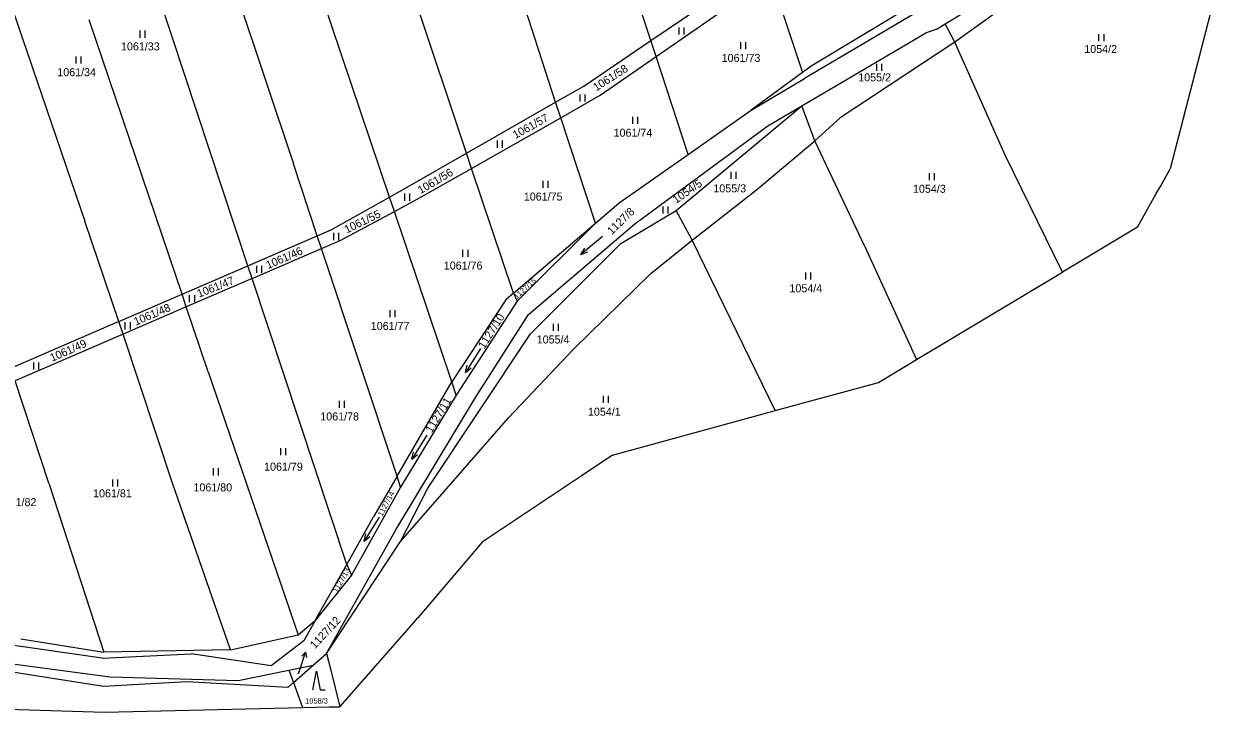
# Model space of a CAD drawing. Extents: x -794142 to -791199, y -1109267 to -1105626.
# Drawn here: x -791483.8 to -791231.1, y -1109118.2 to -1108972 of the extents above; entities that cross this region are included whole.
import ezdxf

# ---------------------------------------------------------------- set-up
doc = ezdxf.new("R2010")
doc.units = 0
for name, color, linetype in [('Komunikace', 7, 'Continuous'), ('Vrstva 1', 7, 'Continuous'), ('Vrstva 14', 7, 'Continuous'), ('Vrstva 16', 7, 'Continuous'), ('Vrstva 23', 7, 'Continuous'), ('Vrstva 4', 7, 'Continuous')]:
    doc.layers.add(name, color=color, linetype=linetype)

msp = doc.modelspace()

# ---------------------------------------------------------------- linework, layer by layer
at = {"layer": 'Komunikace'}
msp.add_line((-791425.42, -1109109.98), (-791424.87, -1109108.32), dxfattribs=at)
at = {"layer": 'Vrstva 1'}
for p, q in [((-791406.1, -1109008.8), (-791438.95, -1108911.62)), ((-791454.92, -1108916.61), (-791426.53, -1109001.71)), ((-791436.19, -1109023.39), (-791469.39, -1108923.1)), ((-791497.78, -1108934.85), (-791470.8, -1109013.94)), ((-791350.58, -1108975.51), (-791363.36, -1108936.25)), ((-791370.82, -1108988.65), (-791384.24, -1108946.84)), ((-791258.33, -1108956.04), (-791286.05, -1108975.86)), ((-791350.58, -1108975.51), (-791326.18, -1108958.88)), ((-791349.46, -1108978.94), (-791325.12, -1108962.07)), ((-791325.12, -1108962.07), (-791318.37, -1108982.33)), ((-791280, -1108961.18), (-791317.94, -1108983.62)), ((-791389.76, -1108999.49), (-791401.54, -1108964.23)), ((-791288.06, -1108972.01), (-791274.69, -1108963.9)), ((-791294.17, -1108967.57), (-791316.56, -1108981)), ((-791450.19, -1109029.44), (-791469.89, -1108971.15)), ((-791292.04, -1108973.81), (-791289.78, -1108973.05)), ((-791289.78, -1108973.05), (-791288.06, -1108972.01)), ((-791286.05, -1108975.86), (-791288.06, -1108972.01)), ((-791364.83, -1108985.22), (-791350.58, -1108975.51)), ((-791349.46, -1108978.94), (-791350.58, -1108975.51)), ((-791318.51, -1108989.39), (-791292.04, -1108973.81)), ((-791286.05, -1108975.86), (-791310.37, -1108991.93)), ((-791275.33, -1108999.92), (-791286.05, -1108975.86)), ((-791361.33, -1108987.16), (-791349.46, -1108978.94)), ((-791342.69, -1108999.76), (-791349.46, -1108978.94)), ((-791316.56, -1108981), (-791318.37, -1108982.33)), ((-791318.37, -1108982.33), (-791329.3, -1108990.34)), ((-791329.3, -1108990.34), (-791317.94, -1108983.62)), ((-791370.82, -1108988.65), (-791364.83, -1108985.22)), ((-791389.76, -1108999.49), (-791370.82, -1108988.65)), ((-791369.74, -1108991.94), (-791370.82, -1108988.65)), ((-791369.74, -1108991.94), (-791361.33, -1108987.16)), ((-791345.22, -1109011.67), (-791318.51, -1108989.39)), ((-791342.69, -1108999.76), (-791329.3, -1108990.34)), ((-791325.74, -1108993.65), (-791318.51, -1108989.39)), ((-791315.73, -1108996.82), (-791318.51, -1108989.39)), ((-791388.68, -1109002.7), (-791369.74, -1108991.94)), ((-791362.36, -1109014.36), (-791369.74, -1108991.94)), ((-791354, -1109014.49), (-791325.74, -1108993.65)), ((-791315.73, -1108996.82), (-791310.37, -1108991.93)), ((-791328.13, -1109007.25), (-791315.73, -1108996.82)), ((-791305.11, -1109019.28), (-791315.73, -1108996.82)), ((-791401.89, -1109006.43), (-791389.76, -1108999.49)), ((-791388.68, -1109002.7), (-791389.76, -1108999.49)), ((-791357.29, -1109010.04), (-791342.69, -1108999.76)), ((-791263.18, -1109024.75), (-791275.33, -1108999.92)), ((-791421.45, -1109017.02), (-791426.53, -1109001.71)), ((-791400.23, -1109009.27), (-791388.68, -1109002.7)), ((-791379.75, -1109029.18), (-791388.68, -1109002.7)), ((-791406.1, -1109008.8), (-791401.89, -1109006.43)), ((-791418.48, -1109015.74), (-791406.1, -1109008.8)), ((-791405.07, -1109011.85), (-791406.1, -1109008.8)), ((-791341.84, -1109017.96), (-791328.13, -1109007.25)), ((-791405.07, -1109011.85), (-791400.23, -1109009.27)), ((-791362.36, -1109014.36), (-791357.29, -1109010.04)), ((-791463.58, -1109035.23), (-791470.8, -1109013.94)), ((-791416.6, -1109018), (-791405.07, -1109011.85)), ((-791392.84, -1109048.04), (-791405.07, -1109011.85)), ((-791356.97, -1109018.62), (-791345.22, -1109011.67)), ((-791341.84, -1109017.96), (-791345.22, -1109011.67)), ((-791421.45, -1109017.02), (-791418.48, -1109015.74)), ((-791379.75, -1109029.18), (-791362.36, -1109014.36)), ((-791379, -1109030.9), (-791362.36, -1109014.36)), ((-791376.55, -1109033.76), (-791354, -1109014.49)), ((-791436.19, -1109023.39), (-791421.45, -1109017.02)), ((-791420.56, -1109019.71), (-791421.45, -1109017.02)), ((-791420.56, -1109019.71), (-791416.6, -1109018)), ((-791376.13, -1109037.8), (-791356.97, -1109018.62)), ((-791350.58, -1109025.02), (-791341.84, -1109017.96)), ((-791324.17, -1109054.09), (-791341.84, -1109017.96)), ((-791435.3, -1109026.08), (-791420.56, -1109019.71)), ((-791404.5, -1109068.08), (-791420.56, -1109019.71)), ((-791305.11, -1109019.28), (-791294.15, -1109043.3)), ((-791450.19, -1109029.44), (-791436.19, -1109023.39)), ((-791435.3, -1109026.08), (-791436.19, -1109023.39)), ((-791435.3, -1109026.08), (-791449.28, -1109032.12)), ((-791415.2, -1109086.82), (-791435.3, -1109026.08)), ((-791350.58, -1109025.02), (-791366.92, -1109040.99)), ((-791379.75, -1109029.18), (-791381.4, -1109030.59)), ((-791379.75, -1109029.18), (-791379, -1109030.9)), ((-791463.58, -1109035.23), (-791450.19, -1109029.44)), ((-791449.28, -1109032.12), (-791450.19, -1109029.44)), ((-791381.4, -1109030.59), (-791392.84, -1109048.04)), ((-791379, -1109030.9), (-791391.95, -1109050.83)), ((-791449.28, -1109032.12), (-791462.67, -1109037.91)), ((-791444.61, -1109045.94), (-791449.28, -1109032.12)), ((-791387.82, -1109051.33), (-791376.55, -1109033.76)), ((-791463.58, -1109035.23), (-791486.5, -1109045.13)), ((-791462.67, -1109037.91), (-791463.58, -1109035.23)), ((-791462.67, -1109037.91), (-791485.62, -1109047.82)), ((-791452.23, -1109069.55), (-791462.67, -1109037.91)), ((-791397.97, -1109070.59), (-791376.13, -1109037.8)), ((-791366.92, -1109040.99), (-791380.83, -1109055.65)), ((-791444.61, -1109045.94), (-791425.48, -1109101.75)), ((-791478.5, -1109069.56), (-791485.62, -1109047.82)), ((-791404.5, -1109068.08), (-791392.84, -1109048.04)), ((-791391.95, -1109050.83), (-791392.84, -1109048.04)), ((-791404.74, -1109079.43), (-791387.82, -1109051.33)), ((-791391.95, -1109050.83), (-791403.74, -1109070.4)), ((-791403.79, -1109081.97), (-791380.83, -1109055.65)), ((-791478.5, -1109069.56), (-791466.81, -1109105.45)), ((-791439.91, -1109104.97), (-791452.23, -1109069.55)), ((-791404.5, -1109068.08), (-791409.5, -1109076.67)), ((-791403.74, -1109070.4), (-791404.5, -1109068.08)), ((-791403.74, -1109070.4), (-791414.21, -1109089.1)), ((-791403.79, -1109081.97), (-791397.97, -1109070.59)), ((-791415.2, -1109086.82), (-791409.5, -1109076.67)), ((-791419.48, -1109105.71), (-791404.74, -1109079.43)), ((-791419.48, -1109105.71), (-791403.79, -1109081.97)), ((-791421.88, -1109098.73), (-791415.2, -1109086.82)), ((-791415.2, -1109086.82), (-791414.21, -1109089.1)), ((-791414.21, -1109089.1), (-791421.88, -1109098.73)), ((-791425.48, -1109101.75), (-791421.88, -1109098.73)), ((-791421.88, -1109098.73), (-791424.28, -1109103.02)), ((-791439.91, -1109104.97), (-791425.48, -1109101.75)), ((-791519.76, -1109103.5), (-791465.44, -1109110.71)), ((-791467.16, -1109106.74), (-791491.85, -1109103.2)), ((-791484.45, -1109102.62), (-791466.81, -1109105.45)), ((-791439.91, -1109104.97), (-791466.81, -1109105.45)), ((-791424.28, -1109103.02), (-791431.26, -1109108.36)), ((-791467.16, -1109106.74), (-791448.27, -1109105.8)), ((-791431.26, -1109108.36), (-791448.27, -1109105.8)), ((-791422.32, -1109108.21), (-791419.48, -1109105.71)), ((-791419.48, -1109105.71), (-791418.67, -1109108.95)), ((-791466.86, -1109112.74), (-791492.63, -1109108.65)), ((-791438.29, -1109111.47), (-791427.5, -1109109.23)), ((-791427.5, -1109109.23), (-791422.32, -1109108.21)), ((-791427.5, -1109109.23), (-791426.52, -1109111.9)), ((-791426.52, -1109111.9), (-791422.32, -1109108.21)), ((-791418.67, -1109108.95), (-791416.64, -1109117.02)), ((-791449.16, -1109111.73), (-791466.86, -1109112.74)), ((-791465.44, -1109110.71), (-791438.29, -1109111.47)), ((-791427.74, -1109112.97), (-791449.16, -1109111.73)), ((-791427.74, -1109112.97), (-791426.52, -1109111.9)), ((-791426.52, -1109111.9), (-791424.57, -1109117.2))]:
    msp.add_line(p, q, dxfattribs=at)
at = {"layer": 'Vrstva 16'}
for p, q in [((-791424.87, -1109108.32), (-791423.923, -1109105.473)), ((-791423.923, -1109105.473), (-791424.713, -1109106.264)), ((-791423.923, -1109105.473), (-791423.764, -1109106.58))]:
    msp.add_line(p, q, dxfattribs=at)
at = {"layer": 'Vrstva 23'}
for p, q in [((-791459.1, -1108974.94), (-791459.1, -1108973.44)), ((-791458.1, -1108973.44), (-791458.1, -1108974.94)), ((-791344.59, -1108974.3), (-791344.59, -1108972.8)), ((-791343.59, -1108972.8), (-791343.59, -1108974.3)), ((-791331.47, -1108977.39), (-791331.47, -1108975.89)), ((-791330.47, -1108975.89), (-791330.47, -1108977.39)), ((-791255.4, -1108975.7), (-791255.4, -1108974.2)), ((-791254.4, -1108974.2), (-791254.4, -1108975.7)), ((-791472.66, -1108980.42), (-791472.66, -1108978.92)), ((-791471.66, -1108978.92), (-791471.66, -1108980.42)), ((-791302.61, -1108982), (-791302.61, -1108980.5)), ((-791301.61, -1108980.5), (-791301.61, -1108982)), ((-791365.64, -1108988.5), (-791365.64, -1108987)), ((-791364.64, -1108987), (-791364.64, -1108988.5)), ((-791354.44, -1108993.27), (-791354.44, -1108991.77)), ((-791353.44, -1108991.77), (-791353.44, -1108993.27)), ((-791383.19, -1108998.31), (-791383.19, -1108996.81)), ((-791382.19, -1108996.81), (-791382.19, -1108998.31)), ((-791333.53, -1109004.94), (-791333.53, -1109003.44)), ((-791332.53, -1109003.44), (-791332.53, -1109004.94)), ((-791291.38, -1109005.18), (-791291.38, -1109003.68)), ((-791290.38, -1109003.68), (-791290.38, -1109005.18)), ((-791373.48, -1109006.83), (-791373.48, -1109005.33)), ((-791372.48, -1109005.33), (-791372.48, -1109006.83)), ((-791402.85, -1109009.56), (-791402.85, -1109008.06)), ((-791401.85, -1109008.06), (-791401.85, -1109009.56)), ((-791348, -1109012.3), (-791348, -1109010.8)), ((-791347, -1109010.8), (-791347, -1109012.3)), ((-791417.97, -1109017.91), (-791417.97, -1109016.41)), ((-791416.97, -1109016.41), (-791416.97, -1109017.91)), ((-791360.852, -1109017.145), (-791365.487, -1109020.954)), ((-791390.5, -1109021.49), (-791390.5, -1109019.99)), ((-791389.5, -1109019.99), (-791389.5, -1109021.49)), ((-791365.487, -1109020.954), (-791364.646, -1109019.616)), ((-791365.487, -1109020.954), (-791364.011, -1109020.388)), ((-791434.28, -1109024.87), (-791434.28, -1109023.37)), ((-791433.28, -1109023.37), (-791433.28, -1109024.87)), ((-791317.65, -1109026.31), (-791317.65, -1109024.81)), ((-791316.65, -1109024.81), (-791316.65, -1109026.31)), ((-791448.57, -1109031.13), (-791448.57, -1109029.63)), ((-791447.57, -1109029.63), (-791447.57, -1109031.13)), ((-791405.97, -1109034.31), (-791405.97, -1109032.81)), ((-791404.97, -1109032.81), (-791404.97, -1109034.31)), ((-791462.23, -1109036.89), (-791462.23, -1109035.39)), ((-791461.23, -1109035.39), (-791461.23, -1109036.89)), ((-791371.29, -1109037.18), (-791371.29, -1109035.68)), ((-791370.29, -1109035.68), (-791370.29, -1109037.18)), ((-791386.804, -1109040.949), (-791389.995, -1109046.03)), ((-791481.67, -1109045.44), (-791481.67, -1109043.94)), ((-791480.67, -1109043.94), (-791480.67, -1109045.44)), ((-791389.995, -1109046.03), (-791389.621, -1109044.494)), ((-791389.995, -1109046.03), (-791388.774, -1109045.026)), ((-791360.67, -1109052.52), (-791360.67, -1109051.02)), ((-791359.67, -1109051.02), (-791359.67, -1109052.52)), ((-791416.75, -1109053.53), (-791416.75, -1109052.03)), ((-791415.75, -1109052.03), (-791415.75, -1109053.53)), ((-791398.174, -1109059.369), (-791401.365, -1109064.45)), ((-791429.22, -1109063.59), (-791429.22, -1109062.09)), ((-791428.22, -1109062.09), (-791428.22, -1109063.59)), ((-791401.365, -1109064.45), (-791400.991, -1109062.914)), ((-791401.365, -1109064.45), (-791400.144, -1109063.446)), ((-791443.52, -1109067.89), (-791443.52, -1109066.39)), ((-791442.52, -1109066.39), (-791442.52, -1109067.89)), ((-791464.86, -1109070.25), (-791464.86, -1109068.75)), ((-791463.86, -1109068.75), (-791463.86, -1109070.25)), ((-791408.304, -1109076.789), (-791411.495, -1109081.87)), ((-791411.495, -1109081.87), (-791411.121, -1109080.334)), ((-791411.495, -1109081.87), (-791410.274, -1109080.866)), ((-791422.41, -1109113.44), (-791421.61, -1109109.44)), ((-791421.61, -1109109.44), (-791420.81, -1109113.44)), ((-791420.81, -1109113.44), (-791419.81, -1109113.44))]:
    msp.add_line(p, q, dxfattribs=at)
at = {"layer": 'Vrstva 4'}
for p, q in [((-791231.13, -1108967.48), (-791240.3, -1109002.82)), ((-791242.28, -1109006.38), (-791240.3, -1109002.82)), ((-791243.3, -1109008.2), (-791242.28, -1109006.38)), ((-791247.18, -1109015.16), (-791243.3, -1109008.2)), ((-791247.18, -1109015.16), (-791263.18, -1109024.75)), ((-791294.15, -1109043.3), (-791263.18, -1109024.75)), ((-791302.25, -1109048.15), (-791295.76, -1109044.26)), ((-791295.76, -1109044.26), (-791294.15, -1109043.3)), ((-791324.17, -1109054.09), (-791302.25, -1109048.15)), ((-791358.73, -1109063.57), (-791325.19, -1109054.37)), ((-791325.19, -1109054.37), (-791324.17, -1109054.09)), ((-791358.73, -1109063.57), (-791365.19, -1109067.89)), ((-791365.19, -1109067.89), (-791386.44, -1109082.09)), ((-791386.44, -1109082.09), (-791400.09, -1109098.16)), ((-791416.64, -1109117.02), (-791400.87, -1109099.07)), ((-791400.87, -1109099.07), (-791400.09, -1109098.16)), ((-791578.9, -1109114.56), (-791466.68, -1109118.19)), ((-791466.68, -1109118.19), (-791424.57, -1109117.2)), ((-791424.57, -1109117.2), (-791418.87, -1109117.07)), ((-791418.87, -1109117.07), (-791416.64, -1109117.02))]:
    msp.add_line(p, q, dxfattribs=at)

# ---------------------------------------------------------------- texts
at = {"layer": 'Vrstva 14'}
for s, height, p in [('1061/33', 1.7, (-791463.146, -1108977.64)), ('1061/73', 1.7, (-791335.552, -1108980.09)), ('1054/2', 1.7, (-791258.514, -1108978.2)), ('1061/34', 1.7, (-791476.681, -1108983.12)), ('1055/2', 1.7, (-791306.545, -1108984.22)), ('1061/74', 1.7, (-791358.498, -1108995.97)), ('1055/3', 1.7, (-791337.315, -1109007.79)), ('1054/3', 1.7, (-791294.904, -1109007.88)), ('1061/75', 1.7, (-791377.578, -1109009.53)), ('1061/76', 1.7, (-791394.582, -1109024.19)), ('1054/4', 1.7, (-791321.15, -1109029.01)), ('1061/77', 1.7, (-791410.089, -1109037.01)), ('1055/4', 1.7, (-791374.831, -1109039.88)), ('1061/78', 1.7, (-791420.812, -1109056.23)), ('1054/1', 1.7, (-791363.948, -1109055.22)), ('1061/79', 1.7, (-791432.752, -1109066.89)), ('1061/80', 1.7, (-791447.754, -1109071.3)), ('1061/81', 1.7, (-791469.078, -1109072.56)), ('1061/82', 1.7, (-791489.335, -1109074.43)), ('1127/12', 0.1, (-791425.673, -1109109.98)), ('1058/3', 1.14, (-791424.021, -1109116.36))]:
    msp.add_text(s, height=height, dxfattribs=at).set_placement(p)
for s, height, rotation, p in [('1061/58', 1.7, 32.64282, (-791362.194, -1108986.369)), ('1061/57', 1.7, 29.00421, (-791379.352, -1108996.489)), ('1061/56', 1.7, 30.29643, (-791399.519, -1109008.191)), ('1054/5', 1.7, 34.77096, (-791345.219, -1109010.254)), ('1061/55', 1.7, 25.82802, (-791415.201, -1109016.534)), ('1127/8', 1.7, 44.18883, (-791358.889, -1109016.903)), ('1061/46', 1.7, 23.4846, (-791431.907, -1109024.111)), ('1061/47', 1.7, 21.62862, (-791446.587, -1109030.18)), ('1127/15', 1.14, 42.73002, (-791379.049, -1109030.545)), ('1061/48', 1.7, 23.00409, (-791460.003, -1109036.099)), ('1127/10', 1.7, 57.58965, (-791385.982, -1109041.173)), ('1061/49', 1.7, 23.7087, (-791477.79, -1109043.798)), ('1127/11', 1.7, 58.5846, (-791397.156, -1109059.011)), ('1127/14', 1.14, 62.77923, (-791407.649, -1109076.715)), ('1127/13', 1.14, 60.52842, (-791417.227, -1109092.945))]:
    msp.add_text(s, height=height, rotation=rotation, dxfattribs=at).set_placement(p)
at = {"layer": 'Vrstva 16'}
msp.add_text('1127/12', height=1.7, rotation=47.15838, dxfattribs=at).set_placement((-791421.95, -1109104.85))

doc.saveas('drawing.dxf')
